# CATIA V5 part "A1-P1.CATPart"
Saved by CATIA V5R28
Part number: Part1
Source: Unknown
Bounding box of the stored display mesh (mm): x -50 to 50, y -70 to 78, z -32.479 to 32.479
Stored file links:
  E:\TP Catia - Documents\Additional Exercise\Contrôle\Problem-3-Section-J\A1-P1.CATPart
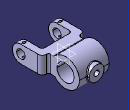
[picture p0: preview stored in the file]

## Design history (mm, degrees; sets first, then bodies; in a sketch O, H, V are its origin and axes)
Body1 (main body)
  Solid1 "Corps principal": solid without history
